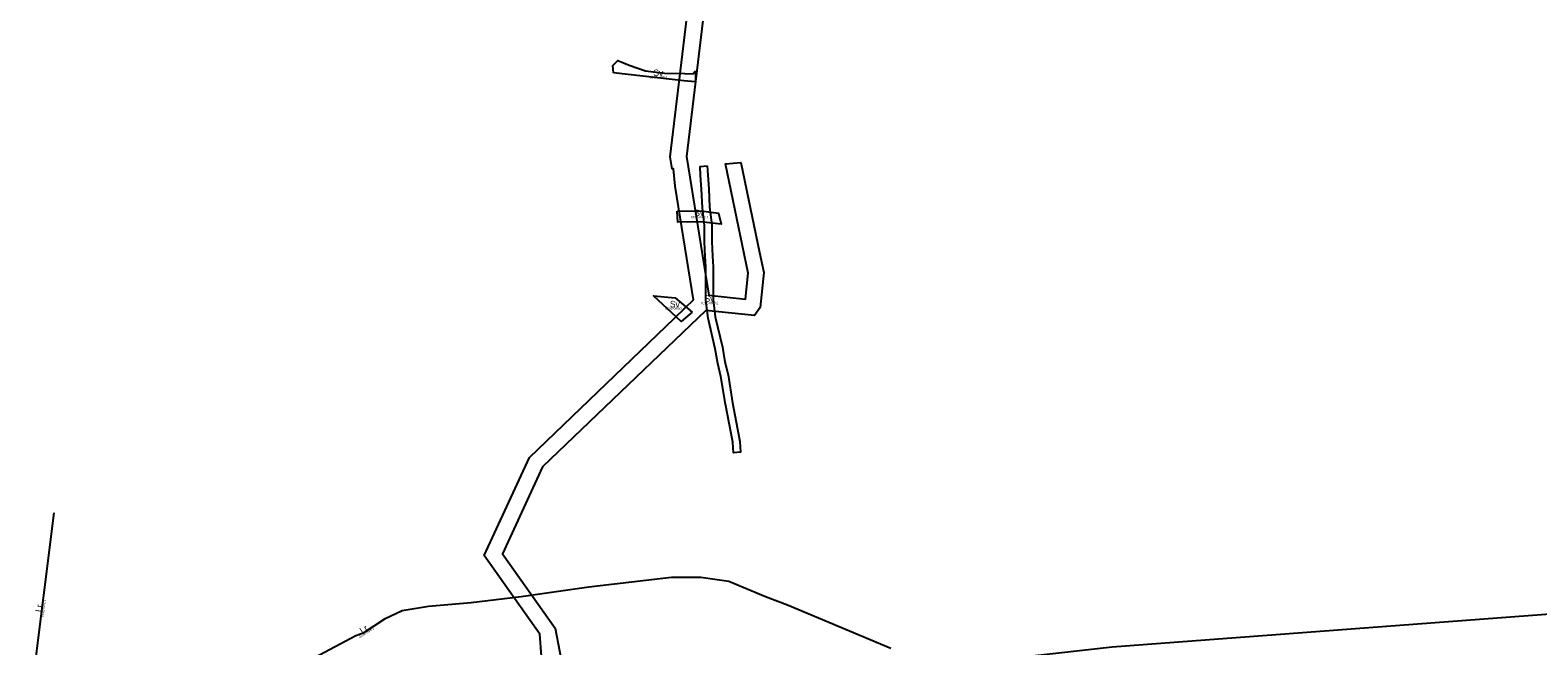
# Model space of a CAD drawing. Extents: x 140791 to 143631, y 6542790 to 6549933.
# Drawn here: x 142221 to 143048, y 6548650 to 6548988 of the extents above; entities that cross this region are included whole.
import ezdxf

# ---------------------------------------------------------------- set-up
doc = ezdxf.new("R2010")
doc.units = 0
for name, color, linetype in [('RATT Aktbeteckning för ledningsrätt', 7, 'Continuous'), ('RATT Aktbeteckning för servitut', 7, 'Continuous'), ('RATT Beteckning för ledningsrätt', 7, 'Continuous'), ('RATT Beteckning för servitut', 7, 'Continuous'), ('RATT Gemensamhetsanläggningsgräns', 7, 'Continuous'), ('RATT Ledningsrätt', 7, 'Continuous'), ('RATT Ledningsrättsgräns', 7, 'Continuous'), ('RATT Servitutsgräns', 7, 'Continuous')]:
    doc.layers.add(name, color=color, linetype=linetype)

msp = doc.modelspace()

# ---------------------------------------------------------------- linework, layer by layer
at = {"layer": 'RATT Gemensamhetsanläggningsgräns'}
msp.add_lwpolyline([(142726.08, 6548612.14), (142763.95, 6548598.2), (142803.23, 6548584.01), (142819.64, 6548578.95), (142837.04, 6548576.19), (142848.88, 6548574.12), (142848.87, 6548575.34), (142860.28, 6548636.97), (143025.98, 6548605.68), (143014.57, 6548544.64), (143013.84, 6548540.03), (143026.22, 6548537.86), (143034, 6548534.95), (143047.93, 6548527.4), (143056.24, 6548520.34), (143062.39, 6548516.19), (143070.24, 6548508.06), (143083.86, 6548556.1), (143113.56, 6548671.83), (142814.85, 6548649.35), (142736.59, 6548640.58), (142726.08, 6548612.14)], dxfattribs=at)
at = {"layer": 'RATT Ledningsrätt'}
msp.add_line((142220.88, 6548618.1), (142234.08, 6548723.11), dxfattribs=at)
msp.add_lwpolyline([(142693.25, 6548648.59), (142636.61, 6548672.42), (142624.51, 6548676.96), (142604.41, 6548685.4), (142589.02, 6548687.54), (142572.86, 6548687.58), (142527.61, 6548682.28), (142490.34, 6548676.86), (142462.94, 6548673.74), (142439.56, 6548671.6), (142425.16, 6548669.28), (142415.43, 6548664.6), (142403.64, 6548656.92), (142399.6, 6548655.51), (142376.91, 6548643.48)], dxfattribs=at)
at = {"layer": 'RATT Ledningsrättsgräns'}
for points in [[(142502.52, 6548632.3), (142500.58, 6548656.41), (142469.99, 6548699.66), (142494.87, 6548753.4), (142574.56, 6548829.9), (142580.34, 6548835.44), (142584.93, 6548839.85), (142574.84, 6548902.37), (142574.06, 6548911.82), (142573.33, 6548911.75), (142572.25, 6548918.44), (142582.83, 6549007.01)], [(142591.71, 6549007.13), (142581.13, 6548918.62), (142593.43, 6548842.42), (142613.58, 6548840.24), (142615.07, 6548854.51), (142602.6, 6548914.48), (142610.87, 6548915.25), (142621.24, 6548865.95), (142623.56, 6548854.93), (142621.51, 6548835.7), (142618.39, 6548831.27), (142591.68, 6548834.13), (142502.16, 6548748.2), (142480.12, 6548700.58), (142509.03, 6548659.71), (142513.82, 6548634.85)]]:
    msp.add_lwpolyline(points, dxfattribs=at)
at = {"layer": 'RATT Servitutsgräns'}
for points in [[(142540.99, 6548964.45), (142540.79, 6548968.45), (142543.39, 6548971.25), (142549.59, 6548968.65), (142558.59, 6548965.65), (142568.99, 6548964.25), (142580.19, 6548964.05), (142584.79, 6548963.85), (142585.79, 6548965.25), (142586.11, 6548965.26), (142586.13, 6548965.26), (142586.11, 6548959.89), (142585.94, 6548959.5), (142579.64, 6548960.14), (142565.19, 6548961.65), (142540.99, 6548964.45)], [(142592.56, 6548913.44), (142592.77, 6548908.4), (142593.4, 6548900.88), (142593.82, 6548890.82), (142595.05, 6548881.04), (142595.06, 6548871.87), (142595.37, 6548863.92), (142595.69, 6548858.11), (142595.7, 6548840.07), (142596.93, 6548830.6), (142600.81, 6548813.89), (142602.18, 6548805.85), (142603.96, 6548798.68), (142606.42, 6548783.33), (142610.45, 6548762.26), (142610.85, 6548756.3), (142606.85, 6548756.03), (142606.48, 6548761.75), (142602.48, 6548782.64), (142600.03, 6548797.88), (142598.26, 6548805.03), (142596.89, 6548813.1), (142592.99, 6548829.89), (142591.7, 6548839.81), (142591.69, 6548858), (142591.38, 6548863.73), (142591.06, 6548871.79), (142591.05, 6548880.79), (142589.83, 6548890.49), (142589.4, 6548900.63), (142588.78, 6548908.15), (142588.56, 6548913.1), (142592.56, 6548913.44)], [(142575.99, 6548888.55), (142589.22, 6548888.76), (142598.69, 6548887.56), (142600.18, 6548881.42), (142588.9, 6548882.76), (142576.42, 6548882.59), (142575.99, 6548888.55)], [(142584.31, 6548833.09), (142578.26, 6548827.94), (142563, 6548842.03), (142574.91, 6548841.01), (142584.31, 6548833.09)]]:
    msp.add_lwpolyline(points, dxfattribs=at)

# ---------------------------------------------------------------- texts
at = {"layer": 'RATT Aktbeteckning för ledningsrätt'}
for s, rotation, p in [('0192-02/2.1', 82.688, (142228.18, 6548665.8)), ('0192-05/8.1', 32.841, (142401.76, 6548654.17))]:
    msp.add_text(s, height=1.3, rotation=rotation, dxfattribs=at).set_placement(p)
at = {"layer": 'RATT Aktbeteckning för servitut'}
for s, p in [('0192-12/6.1', (142561.09, 6548961.48)), ('0192-02/3.1', (142583.55, 6548884.58)), ('0192-08/3.2', (142589.03, 6548837.53)), ('0192-04/60.4', (142569.5, 6548834.54))]:
    msp.add_text(s, height=1.3, dxfattribs=at).set_placement(p)
at = {"layer": 'RATT Beteckning för ledningsrätt'}
for rotation, p in [(82.688, (142227.2, 6548668.42)), (32.841, (142403.13, 6548656.6))]:
    msp.add_text('Lr', height=3.5, rotation=rotation, dxfattribs=at).set_placement(p)
at = {"layer": 'RATT Beteckning för servitut'}
for p in [(142562.95, 6548962.78), (142585.4, 6548885.88), (142571.99, 6548835.84), (142591, 6548838.83)]:
    msp.add_text('Sv', height=3.5, dxfattribs=at).set_placement(p)

doc.saveas('drawing.dxf')
